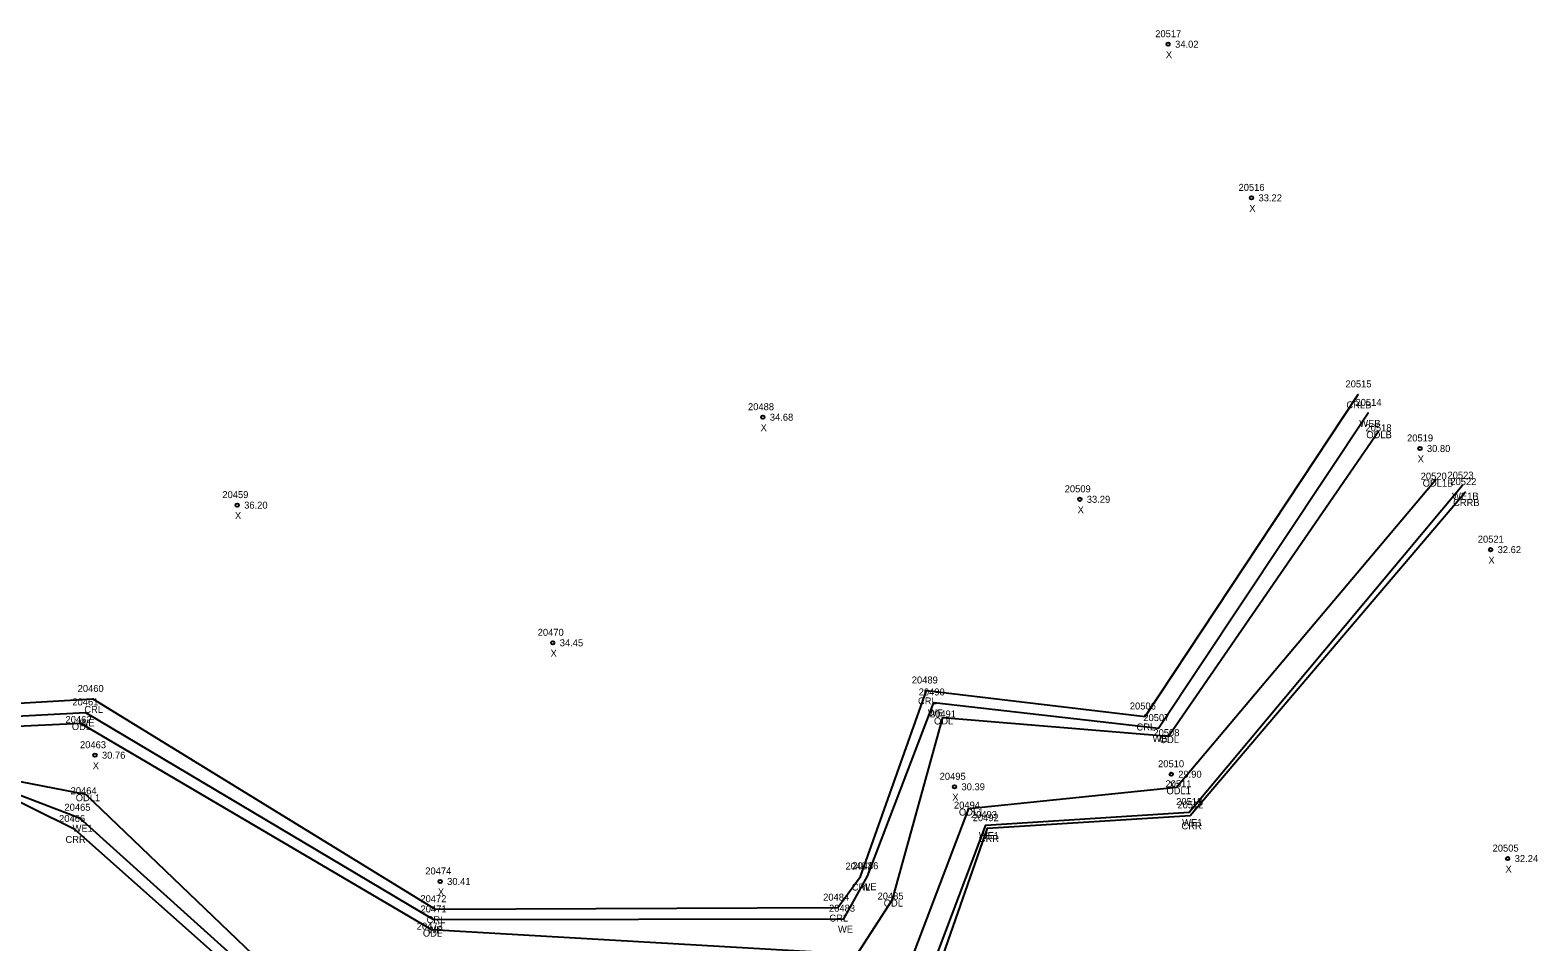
# Model space of a CAD drawing. Extents: x 2445178 to 2446260, y 791158 to 792318.
# Drawn here: x 2445997.4 to 2446212.9, y 791939.9 to 792070.3 of the extents above; entities that cross this region are included whole.
import ezdxf

# ---------------------------------------------------------------- set-up
doc = ezdxf.new("R2010")
doc.units = 0
for name, color, linetype in [('RD_EX_H2O', 7, 'Continuous'), ('RD_EX_H2O_txCode', 7, 'Continuous'), ('RD_Sketch8', 7, 'Continuous'), ('RD_SMD_Locator', 7, 'Continuous')]:
    doc.layers.add(name, color=color, linetype=linetype)

msp = doc.modelspace()

# ---------------------------------------------------------------- linework, layer by layer
at = {"layer": 'RD_EX_H2O'}
for points in [[(2445749.98, 791821.69), (2445784.5, 791816.33), (2445784.5, 791816.33), (2445826.97, 791831.85), (2445864.4, 791840.41), (2445865.35, 791848.28), (2445857.59, 791890.6), (2445862.25, 791903.98), (2445902.88, 791935.07), (2445928.13, 791937.54), (2445982.7, 791973.27), (2446006.36, 791974.66), (2446055.29, 791944.59), (2446112.86, 791944.82), (2446116.06, 791949.26), (2446125.53, 791975.87), (2446156.76, 791972.15), (2446187.24, 792018.21)], [(2445757.3, 791817.48), (2445784.85, 791815.29), (2445827.3, 791828.95), (2445865.88, 791838.48), (2445867.77, 791849.3), (2445858.86, 791890.39), (2445863.96, 791902.52), (2445903.58, 791933.29), (2445928.32, 791935.62), (2445983.75, 791971.59), (2446005.28, 791972.74), (2446055.03, 791943.12), (2446113.69, 791943.23), (2446117.06, 791949.31), (2446126.55, 791974.16), (2446158.67, 791970.49), (2446188.67, 792015.57)], [(2445756.08, 791812.92), (2445785.69, 791811.94), (2445827.07, 791827.18), (2445867.4, 791836.35), (2445869.07, 791850.26), (2445862.28, 791889.54), (2445866.87, 791900.55), (2445904.83, 791930.74), (2445929.24, 791934.15), (2445984.41, 791970.25), (2446004.58, 791971.21), (2446054.77, 791941.67), (2446115.62, 791938.17), (2446120.64, 791945.97), (2446127.84, 791972.01), (2446160.1, 791969.34), (2446190.11, 792012.94)], [(2445746.88, 791778.25), (2445790.91, 791782.86), (2445846.87, 791809.11), (2445896.01, 791824.25), (2445877, 791883.78), (2445912.26, 791916.16), (2445942.78, 791927.77), (2445991.6, 791962.06), (2446003.69, 791956.06), (2446036.32, 791927.07), (2446060.96, 791923.67), (2446122.97, 791923.97), (2446134.24, 791956.18), (2446163.21, 791958.01), (2446202.51, 792004.24)], [(2445748.32, 791780.49), (2445788.24, 791788.44), (2445846, 791811.01), (2445891.85, 791826.96), (2445872.2, 791885.31), (2445911.58, 791917.24), (2445942.41, 791930.41), (2445989.95, 791963.2), (2446004.43, 791957.67), (2446037.13, 791928.19), (2446062.94, 791924.63), (2446122.42, 791925.89), (2446133.98, 791956.62), (2446163.05, 791958.48), (2446202.11, 792005.16)], [(2445752.43, 791785.31), (2445788.27, 791790.61), (2445845.46, 791813.31), (2445889.72, 791828.98), (2445868.44, 791886.37), (2445910.27, 791920.69), (2445939.62, 791931.64), (2445988.31, 791964.33), (2446005.31, 791961.03), (2446034.89, 791932.66), (2446061.86, 791927.42), (2446120.16, 791928.99), (2446131.56, 791958.98), (2446161.23, 791962.03), (2446198.32, 792006.02)]]:
    msp.add_lwpolyline(points, dxfattribs=at)
at = {"layer": 'RD_SMD_Locator'}
for centre, radius in [((2446160.05, 792068.29), 0.25), ((2446171.98, 792046.32), 0.25), ((2446187.24, 792018.21), 0.001), ((2446102.12, 792014.95), 0.25), ((2446188.67, 792015.57), 0.001), ((2446190.11, 792012.94), 0.001), ((2446196.05, 792010.48), 0.25), ((2446198.32, 792006.02), 0.001), ((2446202.11, 792005.16), 0.001), ((2446202.51, 792004.24), 0.001), ((2446026.98, 792002.38), 0.25), ((2446147.43, 792003.21), 0.25), ((2446206.16, 791996.01), 0.25), ((2446072.09, 791982.69), 0.25), ((2446006.36, 791974.66), 0.001), ((2446125.53, 791975.87), 0.001), ((2446126.55, 791974.16), 0.001), ((2446005.28, 791972.74), 0.001), ((2446127.84, 791972.01), 0.001), ((2446156.76, 791972.15), 0.001), ((2446004.58, 791971.21), 0.001), ((2446158.67, 791970.49), 0.001), ((2446160.1, 791969.34), 0.001), ((2446006.65, 791966.61), 0.25), ((2446160.5, 791963.89), 0.25), ((2446005.31, 791961.03), 0.001), ((2446129.52, 791962.1), 0.25), ((2446161.23, 791962.03), 0.001), ((2446131.56, 791958.98), 0.001), ((2446004.43, 791957.67), 0.001), ((2446133.98, 791956.62), 0.001), ((2446163.05, 791958.48), 0.001), ((2446163.21, 791958.01), 0.001), ((2446003.69, 791956.06), 0.001), ((2446134.24, 791956.18), 0.001), ((2446208.6, 791951.83), 0.25), ((2446055.99, 791948.56), 0.25), ((2446116.06, 791949.26), 0.001), ((2446117.06, 791949.31), 0.001), ((2446120.64, 791945.97), 0.001), ((2446055.29, 791944.59), 0.001), ((2446112.86, 791944.82), 0.001), ((2446054.77, 791941.67), 0.001), ((2446055.03, 791943.12), 0.001), ((2446113.69, 791943.23), 0.001)]:
    msp.add_circle(centre, radius, dxfattribs=at)

# ---------------------------------------------------------------- texts
at = {"layer": 'RD_EX_H2O_txCode'}
for s, p in [('20515', (2446185.41, 792019.21)), ('CRLB', (2446185.54, 792016.21)), ('20514', (2446186.84, 792016.57)), ('WEB', (2446187.38, 792013.57)), ('20518', (2446188.27, 792012.94)), ('ODLB', (2446188.39, 792011.94)), ('20520', (2446196.16, 792006.02)), ('20523', (2446199.99, 792006.16)), ('20522', (2446200.4, 792005.24)), ('ODL1B', (2446196.44, 792005.02)), ('WE1B', (2446200.65, 792003.16)), ('CRRB', (2446200.79, 792002.24)), ('20460', (2446004.18, 791975.66)), ('20489', (2446123.41, 791976.87)), ('20490', (2446124.4, 791975.16)), ('20461', (2446003.42, 791973.74)), ('CRL', (2446124.3, 791973.87)), ('20506', (2446154.58, 791973.15)), ('20462', (2446002.44, 791971.21)), ('WE', (2446004.44, 791970.74)), ('CRL', (2446005.13, 791972.66)), ('WE', (2446125.72, 791972.16)), ('20491', (2446126, 791972.01)), ('ODL', (2446126.59, 791971.01)), ('20507', (2446156.51, 791971.49)), ('ODL', (2446003.34, 791970.21)), ('CRL', (2446155.53, 791970.15)), ('20508', (2446157.95, 791969.34)), ('WE', (2446157.83, 791968.49)), ('ODL', (2446158.86, 791968.34)), ('20464', (2446003.17, 791961.03)), ('ODL1', (2446003.9, 791960.03)), ('20511', (2446159.68, 791962.03)), ('ODL1', (2446159.82, 791961.03)), ('20465', (2446002.29, 791958.67)), ('20494', (2446129.44, 791958.98)), ('ODL1', (2446130.15, 791957.98)), ('20513', (2446161.21, 791959.48)), ('20512', (2446161.38, 791959.01)), ('20466', (2446001.52, 791957.06)), ('WE1', (2446003.45, 791955.67)), ('20493', (2446131.87, 791957.62)), ('20492', (2446132.12, 791957.18)), ('CRR', (2446161.96, 791956.01)), ('WE1', (2446162.06, 791956.48)), ('CRR', (2446002.44, 791954.06)), ('WE1', (2446133, 791954.62)), ('CRR', (2446132.99, 791954.18)), ('20487', (2446113.94, 791950.26)), ('20486', (2446114.91, 791950.31)), ('CRL', (2446114.83, 791947.26)), ('WE', (2446116.22, 791947.31)), ('20472', (2446053.17, 791945.59)), ('20484', (2446110.74, 791945.82)), ('20485', (2446118.52, 791945.97)), ('ODL', (2446119.4, 791944.97)), ('20471', (2446053.19, 791944.12)), ('20483', (2446111.58, 791944.23)), ('CRL', (2446111.63, 791942.82)), ('20473', (2446052.65, 791941.67)), ('ODL', (2446053.52, 791940.67)), ('CRL', (2446054.06, 791942.59)), ('WE', (2446054.19, 791941.12)), ('WE', (2446112.86, 791941.23))]:
    msp.add_text(s, height=1, dxfattribs=at).set_placement(p)
at = {"layer": 'RD_Sketch8'}
for s, p in [('20517', (2446158.21, 792069.29)), ('34.02', (2446161.05, 792067.79)), ('X', (2446159.73, 792066.29)), ('20516', (2446170.12, 792047.32)), ('X', (2446171.66, 792044.32)), ('33.22', (2446172.98, 792045.82)), ('20488', (2446100, 792015.95)), ('34.68', (2446103.12, 792014.45)), ('X', (2446101.8, 792012.95)), ('20519', (2446194.21, 792011.48)), ('30.80', (2446197.05, 792009.98)), ('X', (2446195.73, 792008.48)), ('20459', (2446024.86, 792003.38)), ('20509', (2446145.27, 792004.21)), ('36.20', (2446027.98, 792001.88)), ('X', (2446147.12, 792001.21)), ('33.29', (2446148.43, 792002.71)), ('X', (2446026.66, 792000.38)), ('20521', (2446204.32, 791997.01)), ('32.62', (2446207.16, 791995.51)), ('X', (2446205.84, 791994.01)), ('20470', (2446069.94, 791983.69)), ('34.45', (2446073.09, 791982.19)), ('X', (2446071.78, 791980.69)), ('20463', (2446004.51, 791967.61)), ('X', (2446006.33, 791964.61)), ('30.76', (2446007.65, 791966.11)), ('20510', (2446158.62, 791964.89)), ('20495', (2446127.4, 791963.1)), ('29.90', (2446161.5, 791963.39)), ('X', (2446129.2, 791960.1)), ('30.39', (2446130.52, 791961.6)), ('X', (2446160.18, 791961.89)), ('20505', (2446206.44, 791952.83)), ('32.24', (2446209.6, 791951.33)), ('20474', (2446053.87, 791949.56)), ('X', (2446208.28, 791949.83)), ('30.41', (2446056.99, 791948.06)), ('X', (2446055.67, 791946.56))]:
    msp.add_text(s, height=1, dxfattribs=at).set_placement(p)

doc.saveas('drawing.dxf')
